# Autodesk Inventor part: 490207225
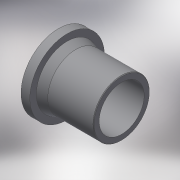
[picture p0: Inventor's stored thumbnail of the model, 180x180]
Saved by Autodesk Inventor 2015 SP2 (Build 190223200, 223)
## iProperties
Created: 2017-07
Part Number: 490207225
Material: Generic
Description: Stub Flange 225
Document SubType Name: Modeling
Designer: Кирилл
Mass: 3431.93 g
Surface Area: 3263.1 cm^2
Volume: 3431.93 cm^3
Density: 1 g/cm^3
Appearance: Default
Author: Кирилл
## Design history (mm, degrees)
derived "490207.ipt"
feature "Solid1::490207.ipt"
tag "TaggingFeature1"
body "Solid1"
other parameters: "d1" = 235, "d2" = 225, "d4" = 268, "d5" = 32, "d6" = 135, "d16" = 225, "d17" = 4.5, "d18" = 4.5, "d19" = 4.5, "d21" = 4.5, "d24" = 4.5, "d25" = 4.5, "d26" = 2.25, "d27" = 0, "d32" = 2.25, "d_" = 225, "L_1" = 135, "D_" = 268, "D_1" = 235, "a_" = 32
